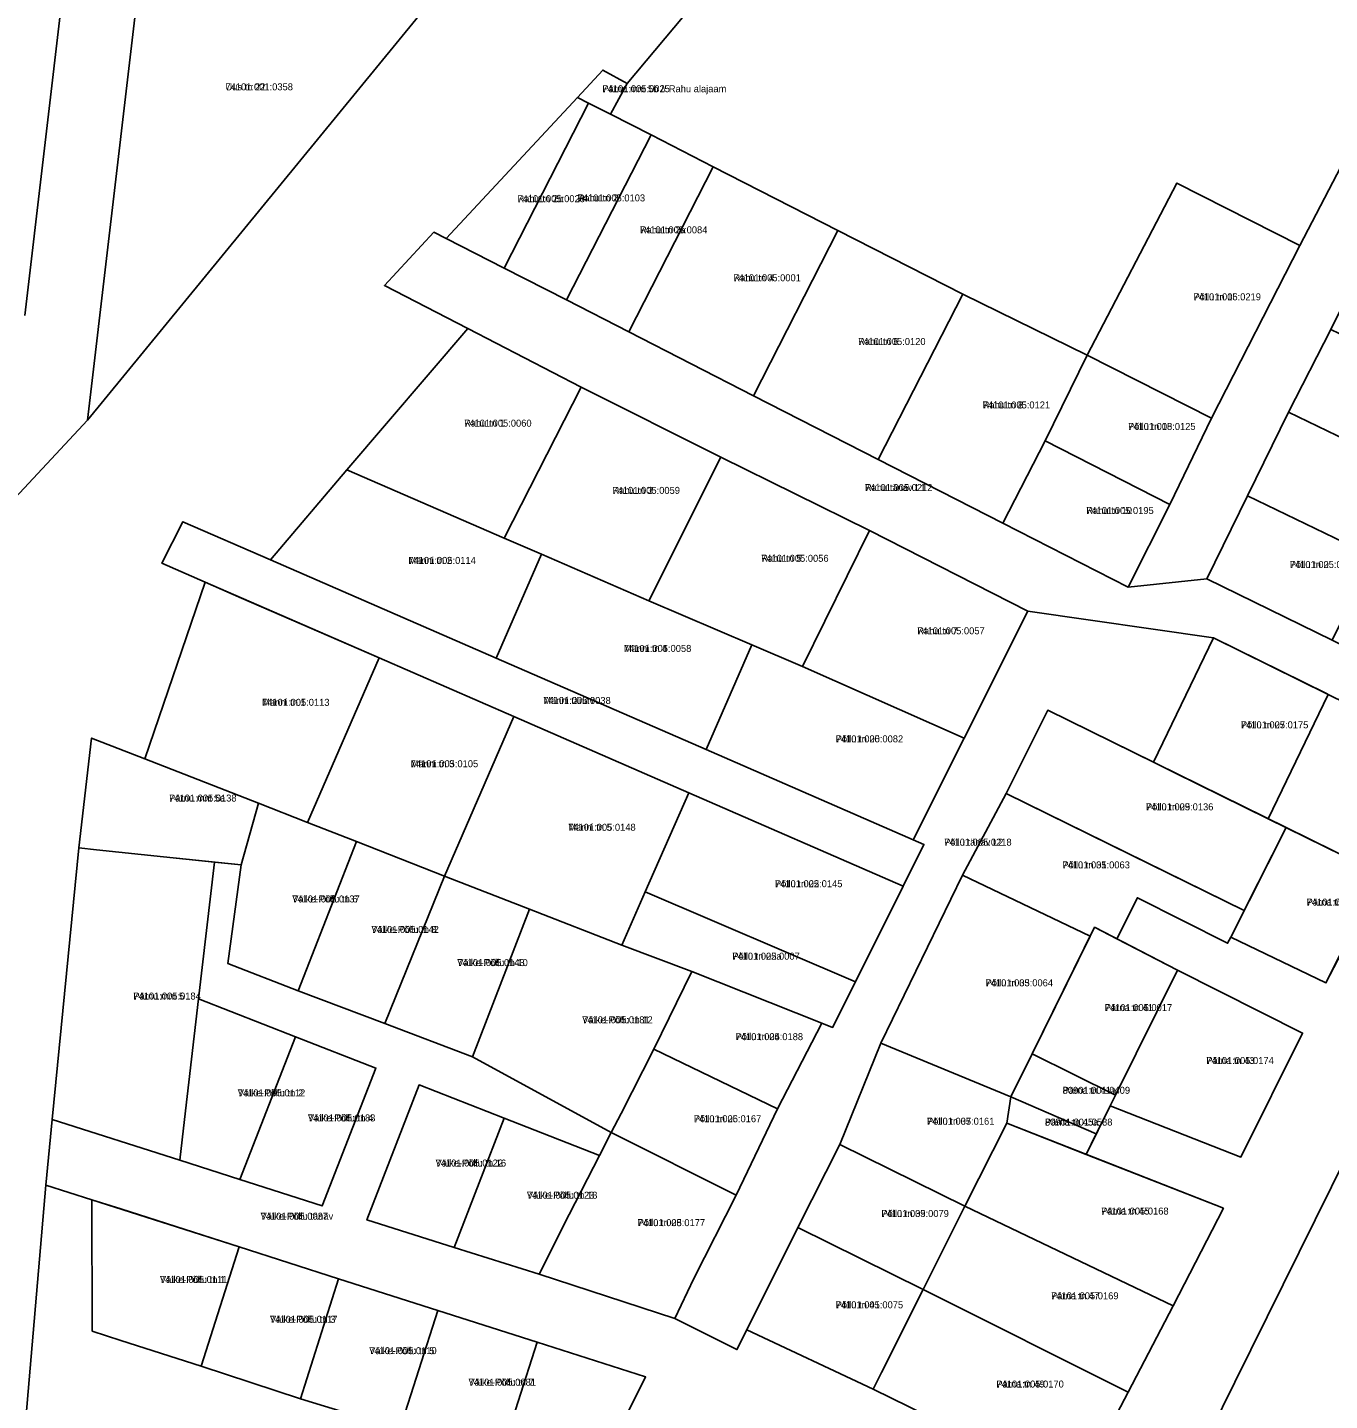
# Model space of a CAD drawing. Extents: x 524000 to 564260, y 6469338 to 6496391.
# Drawn here: x 537498.7 to 537778.5, y 6472932.3 to 6473227.4 of the extents above; entities that cross this region are included whole.
import ezdxf

# ---------------------------------------------------------------- set-up
doc = ezdxf.new("R2010")
doc.units = 0
for name, color, linetype in [('L_AADRESS', 7, 'Continuous'), ('PIIR', 7, 'Continuous'), ('TUNNUS', 7, 'Continuous')]:
    doc.layers.add(name, color=color, linetype=linetype)

msp = doc.modelspace()

# ---------------------------------------------------------------- linework, layer by layer
at = {"layer": 'PIIR'}
for points in [[(537498.07, 6473165.52), (537514.85, 6473308.23), (537520.22, 6473350.65), (537524.6, 6473370.8), (537526.78, 6473380.81), (537539.62, 6473420.34), (537577.28, 6473493.11), (537620.92, 6473576.5), (537640.82, 6473614.87), (537667.76, 6473673.62)], [(537682.27, 6473666.88), (537655.02, 6473607.51), (537635.05, 6473568.99), (537605.52, 6473512.02), (537603.21, 6473507.79), (537591.2, 6473485.77), (537582.5, 6473467.98), (537568.62, 6473441.39), (537554.7, 6473414.79), (537551.83, 6473406.22), (537542.42, 6473377.43), (537535.9, 6473347.26), (537534.65, 6473337.23), (537530.74, 6473306.36), (537527.03, 6473274.9), (537525.8, 6473264.36), (537511.54, 6473143.01), (537493.09, 6473123.14)], [(537493.09, 6473123.14), (537511.54, 6473143.01), (537586.33, 6473234.38), (537592.78, 6473242.33), (537612.46, 6473266.6), (537633.15, 6473290.41), (537643.73, 6473285.32), (537650.13, 6473292.25), (537671.48, 6473315.52), (537692.27, 6473338.35), (537698.92, 6473345.44), (537713.08, 6473371.78), (537726.72, 6473398.56), (537734.46, 6473416.48), (537743.56, 6473445.38), (537756.32, 6473472.54), (537758.5, 6473481.88), (537764.75, 6473505.45), (537762.08, 6473506.82), (537764.79, 6473527.78), (537766.64, 6473549.33), (537775.31, 6473662.75)], [(537458.03, 6473384.13), (537524.6, 6473370.8), (537520.22, 6473350.65), (537514.85, 6473308.23), (537498.07, 6473165.52)], [(537724.12, 6473330.67), (537627.57, 6473215.35), (537622.32, 6473218.26), (537616.88, 6473212.4), (537588.67, 6473182.04), (537586.01, 6473183.4), (537575.4, 6473171.96), (537593.3, 6473162.73), (537567.33, 6473132.37), (537550.87, 6473112.98), (537532.06, 6473121.17), (537527.56, 6473112.26), (537536.89, 6473108.18), (537523.9, 6473070.19), (537512.44, 6473074.66), (537509.71, 6473051.08), (537503.98, 6472992.65), (537502.58, 6472978.59), (537497.89, 6472923.34)], [(537619.41, 6472913.1), (537631.53, 6472937.34), (537608.22, 6472944.8), (537586.87, 6472951.63), (537565.53, 6472958.45), (537544.18, 6472965.29), (537518.7, 6472973.45), (537512.51, 6472975.43), (537502.6, 6472978.58), (537503.98, 6472992.65), (537531.42, 6472983.94), (537544.31, 6472979.82), (537562.02, 6472974.11), (537573.57, 6473003.72), (537556.29, 6473010.48), (537535.44, 6473018.62), (537538.86, 6473048), (537544.58, 6473047.4), (537541.74, 6473026.19), (537556.88, 6473020.36), (537575.47, 6473013.32), (537594.32, 6473006.12), (537624.1, 6472989.86), (537621.6, 6472984.96), (537609.37, 6472989.74), (537601.15, 6472992.95), (537582.83, 6473000.1), (537571.61, 6472971.09), (537590.4, 6472965.17), (537608.66, 6472959.43), (537637.8, 6472949.91), (537651.15, 6472943.21), (537653.27, 6472947.44), (537680.42, 6472934.71), (537722.65, 6472914)], [(537725.47, 6472915.27), (537735.27, 6472934.05), (537744.93, 6472952.61), (537755.72, 6472973.62), (537726.23, 6472985.19), (537731.37, 6472995.65), (537759.5, 6472984.62), (537772.74, 6473011.27), (537745.82, 6473024.82), (537732.85, 6473031.52), (537737.23, 6473040.34), (537756.62, 6473030.56), (537757.32, 6473031.89), (537777.77, 6473022.03), (537789.59, 6473045.41)], [(537737.07, 6472893.34), (537758.2, 6472936.23), (537782.42, 6472985.19)], [(537782.42, 6472985.19), (537758.2, 6472936.23), (537737.07, 6472893.34)]]:
    msp.add_lwpolyline(points, dxfattribs=at)
for points in [[(537911.45, 6473432.19), (537898.77, 6473405), (537878.24, 6473363.63), (537862.56, 6473331.9), (537846.66, 6473299.16), (537830.46, 6473267.01), (537814.16, 6473234.46), (537800.74, 6473207.08), (537787.69, 6473180.48), (537778.82, 6473162.48), (537769.71, 6473144.74), (537760.91, 6473126.77), (537752.14, 6473108.89), (537735.25, 6473107.1), (537744.18, 6473124.88), (537753.17, 6473143.42), (537772.14, 6473180.53), (537824.43, 6473280.98), (537842.16, 6473316.83), (537846.14, 6473325.5), (537858.94, 6473351.56), (537867.79, 6473369.49), (537901.08, 6473436.32)], [(537726.44, 6473156.95), (537699.68, 6473170.07), (537672.88, 6473183.77), (537646.08, 6473197.47), (537632.7, 6473204.36), (537624, 6473208.76), (537627.57, 6473215.35), (537724.12, 6473330.67), (537771.55, 6473307.16), (537797.54, 6473294.29), (537824.43, 6473280.98), (537772.14, 6473180.53), (537745.72, 6473193.99)], [(537586.33, 6473234.38), (537511.54, 6473143.01), (537525.8, 6473264.36)], [(537622.32, 6473218.26), (537627.57, 6473215.35), (537624, 6473208.76), (537619.28, 6473211.17), (537616.88, 6473212.4)], [(537616.88, 6473212.4), (537619.28, 6473211.17), (537601.13, 6473175.67), (537588.67, 6473182.04)], [(537619.28, 6473211.17), (537624, 6473208.76), (537632.7, 6473204.36), (537614.54, 6473168.87), (537601.13, 6473175.67)], [(537614.54, 6473168.87), (537632.7, 6473204.36), (537646.08, 6473197.47), (537627.92, 6473161.97)], [(537646.08, 6473197.47), (537672.88, 6473183.77), (537654.72, 6473148.27), (537627.92, 6473161.97)], [(537745.72, 6473193.99), (537772.14, 6473180.53), (537753.17, 6473143.42), (537726.44, 6473156.95)], [(537588.67, 6473182.04), (537601.13, 6473175.67), (537614.54, 6473168.87), (537627.92, 6473161.97), (537654.72, 6473148.27), (537681.52, 6473134.57), (537708.32, 6473120.87), (537735.25, 6473107.1), (537752.14, 6473108.89), (537779.08, 6473095.69), (537807.87, 6473081.6), (537802.47, 6473072.14), (537778.25, 6473084.07), (537753.6, 6473096.21), (537713.66, 6473101.96), (537679.62, 6473119.33), (537647.7, 6473135.08), (537617.7, 6473150.13), (537593.3, 6473162.73), (537575.4, 6473171.96), (537586.01, 6473183.4)], [(537672.88, 6473183.77), (537699.68, 6473170.07), (537681.52, 6473134.57), (537654.72, 6473148.27)], [(537699.68, 6473170.07), (537726.44, 6473156.95), (537717.38, 6473138.58), (537708.32, 6473120.87), (537681.52, 6473134.57)], [(537593.3, 6473162.73), (537617.7, 6473150.13), (537601.11, 6473117.68), (537567.33, 6473132.37)], [(537778.82, 6473162.48), (537805.67, 6473149.63), (537796.72, 6473131.69), (537769.71, 6473144.74)], [(537717.38, 6473138.58), (537726.44, 6473156.95), (537753.17, 6473143.42), (537744.18, 6473124.88)], [(537601.11, 6473117.68), (537617.7, 6473150.13), (537647.7, 6473135.08), (537632.23, 6473104.18), (537609.12, 6473114.19)], [(537769.71, 6473144.74), (537796.72, 6473131.69), (537787.92, 6473113.72), (537760.91, 6473126.77)], [(537717.38, 6473138.58), (537744.18, 6473124.88), (537735.25, 6473107.1), (537708.32, 6473120.87)], [(537679.62, 6473119.33), (537665.24, 6473090.06), (537654.39, 6473094.7), (537632.23, 6473104.18), (537647.7, 6473135.08)], [(537567.33, 6473132.37), (537601.11, 6473117.68), (537609.12, 6473114.19), (537599.38, 6473091.86), (537550.87, 6473112.98)], [(537760.91, 6473126.77), (537787.92, 6473113.72), (537779.08, 6473095.69), (537752.14, 6473108.89)], [(537532.06, 6473121.17), (537550.87, 6473112.98), (537599.38, 6473091.86), (537644.56, 6473072.21), (537689.07, 6473052.8), (537691.35, 6473051.81), (537686.88, 6473042.85), (537640.84, 6473062.92), (537603.23, 6473079.32), (537574.26, 6473091.9), (537544.68, 6473104.78), (537536.89, 6473108.18), (537527.56, 6473112.26)], [(537679.62, 6473119.33), (537713.66, 6473101.96), (537699.99, 6473074.64), (537665.24, 6473090.06)], [(537609.12, 6473114.19), (537632.23, 6473104.18), (537654.39, 6473094.7), (537644.56, 6473072.21), (537599.38, 6473091.86)], [(537523.9, 6473070.19), (537536.89, 6473108.18), (537574.26, 6473091.9), (537558.85, 6473056.53), (537548.3, 6473060.65)], [(537753.6, 6473096.21), (537740.72, 6473069.47), (537717.95, 6473080.67), (537709.05, 6473062.76), (537699.67, 6473045.19), (537682.11, 6473009.1), (537673.28, 6472987.29), (537664.28, 6472969.49), (537653.27, 6472947.44), (537651.15, 6472943.21), (537637.8, 6472949.91), (537641.92, 6472958.47), (537650.96, 6472976.39), (537659.87, 6472994.97), (537669.39, 6473013.4), (537671.72, 6473012.47), (537676.63, 6473022.31), (537686.88, 6473042.85), (537691.35, 6473051.81), (537689.07, 6473052.8), (537699.99, 6473074.64), (537713.66, 6473101.96)], [(537753.6, 6473096.21), (537777.89, 6473084.25), (537778.25, 6473084.07), (537765.37, 6473057.33), (537745.15, 6473067.29), (537740.72, 6473069.47)], [(537558.85, 6473056.53), (537574.26, 6473091.9), (537603.23, 6473079.32), (537588.3, 6473045.02), (537569.4, 6473052.41)], [(537654.39, 6473094.7), (537665.24, 6473090.06), (537699.99, 6473074.64), (537689.07, 6473052.8), (537644.56, 6473072.21)], [(537765.37, 6473057.33), (537778.25, 6473084.07), (537802.47, 6473072.14), (537789.59, 6473045.41)], [(537717.95, 6473080.67), (537769.18, 6473055.47), (537760.2, 6473037.61), (537709.05, 6473062.76)], [(537588.3, 6473045.02), (537603.23, 6473079.32), (537640.84, 6473062.92), (537631.45, 6473041.61), (537626.41, 6473030.18), (537606.6, 6473037.87)], [(537513.5, 6473050.63), (537509.71, 6473051.08), (537512.44, 6473074.66), (537523.9, 6473070.19), (537548.3, 6473060.65), (537544.58, 6473047.4), (537527.92, 6473049.16)], [(537686.88, 6473042.85), (537676.63, 6473022.31), (537631.45, 6473041.61), (537640.84, 6473062.92)], [(537709.05, 6473062.76), (537735.97, 6473049.52), (537760.2, 6473037.61), (537757.32, 6473031.89), (537756.62, 6473030.56), (537737.23, 6473040.34), (537732.85, 6473031.52), (537728.05, 6473034), (537727.09, 6473032.07), (537699.67, 6473045.19)], [(537541.74, 6473026.19), (537544.58, 6473047.4), (537548.3, 6473060.65), (537558.85, 6473056.53), (537569.4, 6473052.41), (537556.88, 6473020.36)], [(537757.32, 6473031.89), (537769.18, 6473055.47), (537789.88, 6473045.27), (537777.77, 6473022.03)], [(537509.71, 6473051.08), (537513.5, 6473050.63), (537527.92, 6473049.16), (537538.86, 6473048), (537535.44, 6473018.62), (537532.43, 6472992.68), (537531.42, 6472983.94), (537503.98, 6472992.65)], [(537569.4, 6473052.41), (537588.3, 6473045.02), (537575.47, 6473013.32), (537556.88, 6473020.36)], [(537588.3, 6473045.02), (537606.6, 6473037.87), (537594.32, 6473006.12), (537575.47, 6473013.32)], [(537699.67, 6473045.19), (537727.09, 6473032.07), (537714.59, 6473006.83), (537710.02, 6472997.56), (537682.11, 6473009.1)], [(537626.41, 6473030.18), (537631.45, 6473041.61), (537676.63, 6473022.31), (537671.72, 6473012.47), (537669.39, 6473013.4), (537641.45, 6473024.52)], [(537606.6, 6473037.87), (537626.41, 6473030.18), (537641.45, 6473024.52), (537633.3, 6473007.81), (537626.27, 6472993.94), (537624.1, 6472989.86), (537594.32, 6473006.12)], [(537728.05, 6473034), (537745.82, 6473024.82), (537732.5, 6472997.95), (537714.59, 6473006.83)], [(537641.45, 6473024.52), (537669.39, 6473013.4), (537659.87, 6472994.97), (537633.3, 6473007.81)], [(537772.74, 6473011.27), (537759.5, 6472984.62), (537731.37, 6472995.65), (537732.5, 6472997.95), (537745.82, 6473024.82)], [(537532.43, 6472992.68), (537535.44, 6473018.62), (537556.29, 6473010.48), (537544.31, 6472979.82), (537531.42, 6472983.94)], [(537573.57, 6473003.72), (537562.02, 6472974.11), (537544.31, 6472979.82), (537556.29, 6473010.48)], [(537626.27, 6472993.94), (537633.3, 6473007.81), (537659.87, 6472994.97), (537650.96, 6472976.39), (537624.1, 6472989.86)], [(537682.11, 6473009.1), (537710.02, 6472997.56), (537709.15, 6472991.89), (537700.17, 6472974.02), (537673.28, 6472987.29)], [(537714.59, 6473006.83), (537732.5, 6472997.95), (537731.37, 6472995.65), (537728.39, 6472989.59), (537710.02, 6472997.56)], [(537582.83, 6473000.1), (537601.15, 6472992.95), (537590.4, 6472965.17), (537571.61, 6472971.09)], [(537710.02, 6472997.56), (537728.39, 6472989.59), (537726.23, 6472985.19), (537709.15, 6472991.89)], [(537601.15, 6472992.95), (537609.37, 6472989.74), (537621.6, 6472984.96), (537615.11, 6472972.24), (537608.66, 6472959.43), (537590.4, 6472965.17)], [(537744.93, 6472952.61), (537700.17, 6472974.02), (537709.15, 6472991.89), (537755.72, 6472973.62)], [(537650.96, 6472976.39), (537641.92, 6472958.47), (537637.8, 6472949.91), (537608.66, 6472959.43), (537615.11, 6472972.24), (537621.6, 6472984.96), (537624.1, 6472989.86)], [(537673.28, 6472987.29), (537700.17, 6472974.02), (537691.2, 6472956.15), (537664.28, 6472969.49)], [(537499.25, 6472864.49), (537497.89, 6472923.34), (537502.58, 6472978.59), (537512.49, 6472975.44), (537512.59, 6472947.21), (537518.76, 6472945.2), (537536.02, 6472939.64), (537557.36, 6472932.63), (537578.69, 6472926.13), (537596.71, 6472920.37), (537574.61, 6472872.78), (537593.6, 6472861.73), (537579.56, 6472832.61), (537553.06, 6472843.13), (537530.31, 6472852.17)], [(537512.59, 6472947.21), (537512.49, 6472975.44), (537544.18, 6472965.29), (537536.02, 6472939.64), (537518.76, 6472945.2)], [(537700.17, 6472974.02), (537744.93, 6472952.61), (537735.27, 6472934.05), (537691.2, 6472956.15)], [(537664.28, 6472969.49), (537691.2, 6472956.15), (537682.22, 6472938.28), (537680.42, 6472934.71), (537653.27, 6472947.44)], [(537544.18, 6472965.29), (537565.53, 6472958.45), (537557.36, 6472932.63), (537536.02, 6472939.64)], [(537565.53, 6472958.45), (537586.87, 6472951.63), (537578.71, 6472926.12), (537557.36, 6472932.63)], [(537682.22, 6472938.28), (537691.2, 6472956.15), (537735.27, 6472934.05), (537725.47, 6472915.27), (537722.65, 6472914), (537680.42, 6472934.71)], [(537586.87, 6472951.63), (537608.22, 6472944.8), (537600.05, 6472919.3), (537578.71, 6472926.13)], [(537608.22, 6472944.8), (537631.53, 6472937.34), (537619.41, 6472913.1), (537600.05, 6472919.3)]]:
    msp.add_lwpolyline(points, close=True, dxfattribs=at)

# ---------------------------------------------------------------- texts
at = {"layer": 'L_AADRESS'}
for s, p in [('Uus tn 22', (537541.22, 6473213.92)), ('Pärnu mnt 5b // Rahu alajaam', (537622.24, 6473213.51)), ('Rahu tn 2b', (537603.98, 6473189.87)), ('Rahu tn 2', (537616.92, 6473190.03)), ('Rahu tn 2a', (537630.31, 6473183.17)), ('Rahu tn 4', (537650.4, 6473172.87)), ('Põllu tn 16', (537749.29, 6473168.78)), ('Rahu tn 6', (537677.2, 6473159.17)), ('Rahu tn 8', (537703.98, 6473145.53)), ('Rahu tn 1', (537592.52, 6473141.62)), ('Põllu tn 18', (537735.24, 6473140.91)), ('Rahu tn 3', (537624.41, 6473127.17)), ('Rahu tänav L1', (537678.67, 6473127.77)), ('Rahu tn 10', (537726.24, 6473122.84)), ('Männi tn 2', (537580.54, 6473112.12)), ('Rahu tn 5', (537656.36, 6473112.57)), ('Põllu tn 25', (537769.99, 6473111.23)), ('Rahu tn 7', (537689.91, 6473096.99)), ('Männi tn 4', (537626.85, 6473093.2)), ('Männi tn 1', (537549.08, 6473081.61)), ('Männi tänav', (537609.53, 6473082.01)), ('Põllu tn 27', (537759.48, 6473076.77)), ('Põllu tn 20', (537672.39, 6473073.75)), ('Männi tn 3', (537581.04, 6473068.41)), ('Pärnu mnt 5a', (537529.1, 6473061.03)), ('Põllu tn 29', (537739.07, 6473059.14)), ('Männi tn 5', (537614.89, 6473054.75)), ('Põllu tänav L2', (537695.7, 6473051.55)), ('Põllu tn 31', (537721.12, 6473046.66)), ('Põllu tn 22', (537659.33, 6473042.62)), ('Väike-Põllu tn 6', (537555.57, 6473039.34)), ('Pärna tn 37', (537773.6, 6473038.67)), ('Väike-Põllu tn 8', (537572.59, 6473032.79)), ('Väike-Põllu tn 10', (537591.04, 6473025.66)), ('Põllu tn 22a', (537650.16, 6473027.04)), ('Põllu tn 33', (537704.6, 6473021.32)), ('Pärnu mnt 5', (537521.42, 6473018.47)), ('Pärna tn 41', (537730.21, 6473015.99)), ('Väike-Põllu tn 12', (537617.89, 6473013.37)), ('Põllu tn 24', (537650.87, 6473009.74)), ('Pärna tn 43', (537752.05, 6473004.61)), ('Väike-Põllu tn 2', (537543.86, 6472997.65)), ('Pärna tn 41a', (537721.16, 6472998.21)), ('Väike-Põllu tn 4', (537558.94, 6472992.27)), ('Põllu tn 26', (537641.89, 6472992.1)), ('Põllu tn 37', (537692, 6472991.56)), ('Pärna tn 45a', (537717.37, 6472991.38)), ('Väike-Põllu tn 16', (537586.38, 6472982.58)), ('Väike-Põllu tn 18', (537606, 6472975.66)), ('Pärna tn 45', (537729.44, 6472972.25)), ('Väike-Põllu tänav', (537548.77, 6472971.14)), ('Põllu tn 28', (537629.81, 6472969.76)), ('Põllu tn 39', (537682.21, 6472971.72)), ('Väike-Põllu tn 1', (537527.13, 6472957.54)), ('Põllu tn 41', (537672.38, 6472952.1)), ('Pärna tn 47', (537718.68, 6472954.04)), ('Väike-Põllu tn 3', (537550.78, 6472948.99)), ('Väike-Põllu tn 5', (537572.11, 6472942.24)), ('Väike-Põllu tn 7', (537593.46, 6472935.46)), ('Pärna tn 49', (537706.92, 6472935.07))]:
    msp.add_text(s, height=1.5, dxfattribs=at).set_placement(p)
at = {"layer": 'TUNNUS'}
for s, p in [('74101:001:0358', (537541.22, 6473213.92)), ('74101:005:0025', (537622.24, 6473213.51)), ('74101:005:0028', (537603.98, 6473189.87)), ('74101:005:0103', (537616.92, 6473190.03)), ('74101:005:0084', (537630.31, 6473183.17)), ('74101:005:0001', (537650.4, 6473172.87)), ('74101:005:0219', (537749.29, 6473168.78)), ('74101:005:0120', (537677.2, 6473159.17)), ('74101:005:0121', (537703.98, 6473145.53)), ('74101:005:0060', (537592.52, 6473141.62)), ('74101:005:0125', (537735.24, 6473140.91)), ('74101:005:0059', (537624.41, 6473127.17)), ('74101:005:0212', (537678.67, 6473127.77)), ('74101:005:0195', (537726.24, 6473122.84)), ('74101:005:0114', (537580.54, 6473112.12)), ('74101:005:0056', (537656.36, 6473112.57)), ('74101:005:0158', (537769.99, 6473111.23)), ('74101:005:0057', (537689.91, 6473096.99)), ('74101:005:0058', (537626.85, 6473093.2)), ('74101:005:0113', (537549.08, 6473081.61)), ('74101:005:0038', (537609.53, 6473082.01)), ('74101:005:0175', (537759.48, 6473076.77)), ('74101:005:0082', (537672.39, 6473073.75)), ('74101:005:0105', (537581.04, 6473068.41)), ('74101:005:0138', (537529.1, 6473061.03)), ('74101:005:0136', (537739.07, 6473059.14)), ('74101:005:0148', (537614.89, 6473054.75)), ('74101:005:0218', (537695.7, 6473051.55)), ('74101:005:0063', (537721.12, 6473046.66)), ('74101:005:0145', (537659.33, 6473042.62)), ('74101:005:0137', (537555.57, 6473039.34)), ('74101:005:0165', (537773.6, 6473038.67)), ('74101:005:0142', (537572.59, 6473032.79)), ('74101:005:0143', (537591.04, 6473025.66)), ('74101:005:0007', (537650.16, 6473027.04)), ('74101:005:0064', (537704.6, 6473021.32)), ('74101:005:0184', (537521.42, 6473018.47)), ('74101:005:0017', (537730.21, 6473015.99)), ('74101:005:0181', (537617.89, 6473013.37)), ('74101:005:0188', (537650.87, 6473009.74)), ('74101:005:0174', (537752.05, 6473004.61)), ('74101:005:0112', (537543.86, 6472997.65)), ('80901:001:0409', (537721.16, 6472998.21)), ('74101:005:0183', (537558.94, 6472992.27)), ('74101:005:0167', (537641.89, 6472992.1)), ('74101:005:0161', (537692, 6472991.56)), ('80901:001:0588', (537717.37, 6472991.38)), ('74101:005:0122', (537586.38, 6472982.58)), ('74101:005:0123', (537606, 6472975.66)), ('74101:005:0168', (537729.44, 6472972.25)), ('74101:005:0037', (537548.77, 6472971.14)), ('74101:005:0177', (537629.81, 6472969.76)), ('74101:005:0079', (537682.21, 6472971.72)), ('74101:005:0111', (537527.13, 6472957.54)), ('74101:005:0075', (537672.38, 6472952.1)), ('74101:005:0169', (537718.68, 6472954.04)), ('74101:005:0117', (537550.78, 6472948.99)), ('74101:005:0110', (537572.11, 6472942.24)), ('74101:005:0081', (537593.46, 6472935.46)), ('74101:005:0170', (537706.92, 6472935.07))]:
    msp.add_text(s, height=1.5, dxfattribs=at).set_placement(p)

doc.saveas('drawing.dxf')
